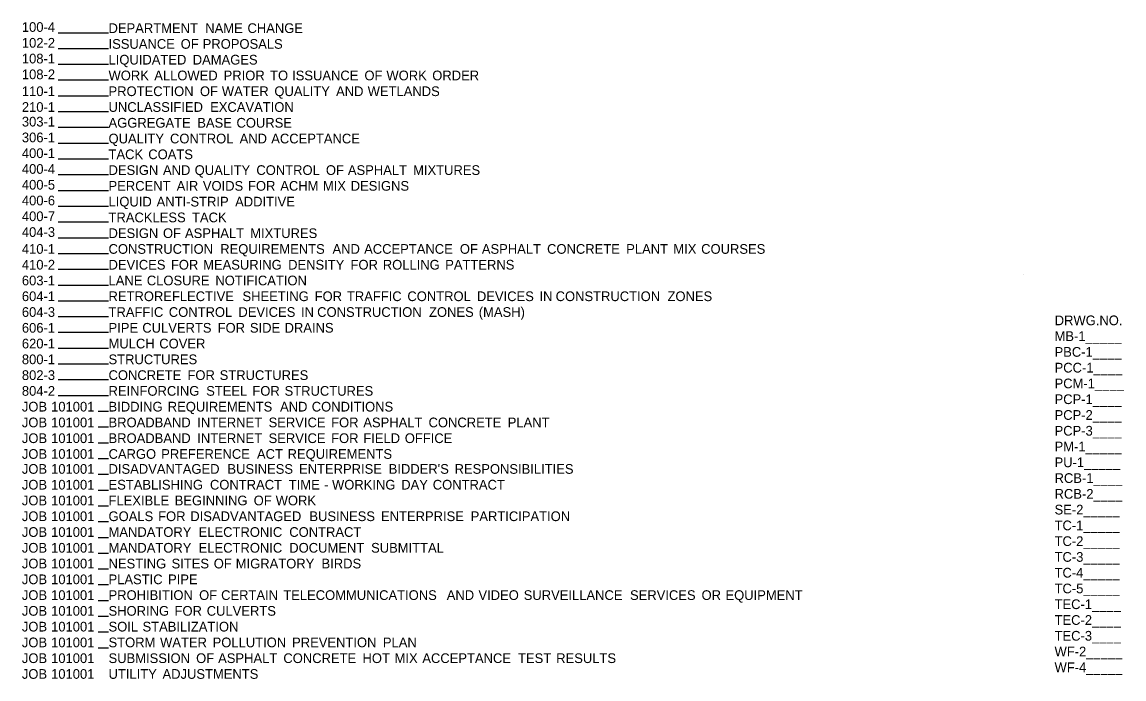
# Model space of a CAD drawing. Extents: x -1197 to 1681, y -1031 to 1021.
# Drawn here: x -1189 to 174, y -760 to 52 of the extents above; entities that cross this region are included whole.
import ezdxf

# ---------------------------------------------------------------- set-up
doc = ezdxf.new("R2010")
doc.units = 0
doc.layers.add('Default', color=7, linetype='Continuous')

msp = doc.modelspace()

# ---------------------------------------------------------------- linework, layer by layer
at = {"layer": 'Default'}
for p, q in [((-1081.7, 38.3), (-1144, 38.3)), ((-1081.7, 18.8), (-1144, 18.8)), ((-1081.7, -0.7), (-1144, -0.7)), ((-1081.7, -20.2), (-1144, -20.2)), ((-1081.7, -39.7), (-1144, -39.7)), ((-1081.7, -59.2), (-1144, -59.2)), ((-1081.7, -78.7), (-1144, -78.7)), ((-1081.7, -98.2), (-1144, -98.2)), ((-1081.7, -117.7), (-1144, -117.7)), ((-1081.7, -137.2), (-1144, -137.2)), ((-1081.7, -156.7), (-1144, -156.7)), ((-1081.7, -176.2), (-1144, -176.2)), ((-1081.7, -195.7), (-1144, -195.7)), ((-1081.7, -215.2), (-1144, -215.2)), ((-1081.7, -234.7), (-1144, -234.7)), ((-1081.7, -254.2), (-1144, -254.2)), ((50.5, -260), (50.5, -260)), ((-1081.7, -273.7), (-1144, -273.7)), ((-1081.7, -293.2), (-1144, -293.2)), ((-1081.7, -312.7), (-1144, -312.7)), ((-1081.7, -332.2), (-1144, -332.2)), ((-1081.7, -351.7), (-1144, -351.7)), ((-1081.7, -371.2), (-1144, -371.2)), ((-1081.7, -390.7), (-1144.2, -390.7)), ((-1081.7, -410.2), (-1144.2, -410.2)), ((-1081.7, -429.7), (-1094.4, -429.7)), ((-1081.7, -449.2), (-1094.4, -449.2)), ((-1081.7, -468.7), (-1094.4, -468.7)), ((-1081.7, -488.2), (-1094.4, -488.2)), ((-1081.7, -507.7), (-1094.4, -507.7)), ((-1081.7, -527.2), (-1094.4, -527.2)), ((-1081.7, -546.7), (-1094.4, -546.7)), ((-1081.7, -566.2), (-1094.4, -566.2)), ((-1081.7, -585.7), (-1094.4, -585.7)), ((-1081.7, -605.2), (-1094.4, -605.2)), ((-1081.7, -624.7), (-1094.4, -624.7)), ((-1081.7, -644.2), (-1094.4, -644.2)), ((-1081.7, -663.7), (-1094.4, -663.7)), ((-1081.7, -683.2), (-1094.4, -683.2)), ((-1081.7, -702.7), (-1094.4, -702.7)), ((-1081.7, -722.2), (-1094.4, -722.2))]:
    msp.add_line(p, q, dxfattribs=at)

# ---------------------------------------------------------------- texts
for s, p in [('100-4', (-1188.9, 39.7)), ('DEPARTMENT', (-1081.7, 38.3)), (' NAME', (-966.5, 38.3)), (' CHANGE', (-914.3, 38.3)), ('102-2', (-1188.9, 20.2)), ('ISSUANCE', (-1081.7, 18.8)), (' OF', (-996.9, 18.8)), (' PROPOSALS', (-969.7, 18.8)), ('108-1', (-1188.9, 0.7)), ('LIQUIDATED', (-1081.7, -0.7)), (' DAMAGES', (-982, -0.7)), ('108-2', (-1188.9, -18.8)), ('WORK', (-1081.7, -20.2)), (' ALLOWED', (-1029.6, -20.2)), (' PRIOR', (-943.8, -20.2)), (' TO', (-886.3, -20.2)), (' ISSUANCE', (-859.1, -20.2)), (' OF', (-769.6, -20.2)), (' WORK', (-742.4, -20.2)), (' ORDER', (-685.7, -20.2)), ('110-1', (-1188.9, -39.7)), ('PROTECTION', (-1081.7, -39.7)), (' OF', (-973.1, -39.7)), (' WATER', (-946, -39.7)), (' QUALITY', (-881, -39.7)), (' AND', (-804.7, -39.7)), (' WETLANDS', (-765.6, -39.7)), ('210-1', (-1188.9, -59.2)), ('UNCLASSIFIED', (-1081.7, -59.2)), (' EXCAVATION', (-960.5, -59.2)), ('303-1', (-1188.9, -77.3)), ('AGGREGATE', (-1081.7, -78.7)), (' BASE', (-976.4, -78.7)), (' COURSE', (-927.9, -78.7)), ('306-1', (-1188.9, -96.8)), ('QUALITY', (-1081.7, -98.2)), (' CONTROL', (-1010.1, -98.2)), (' AND', (-924, -98.2)), (' ACCEPTANCE', (-884.9, -98.2)), ('400-1', (-1188.9, -116.3)), ('TACK', (-1081.7, -117.7)), (' COATS', (-1037, -117.7)), ('400-4', (-1188.9, -135.8)), ('DESIGN', (-1081.7, -137.2)), (' AND', (-1018.8, -137.2)), (' QUALITY', (-979.6, -137.2)), (' CONTROL', (-903.3, -137.2)), (' OF', (-817.3, -137.2)), (' ASPHALT', (-790.1, -137.2)), (' MIXTURES', (-709.4, -137.2)), ('400-5', (-1188.9, -155.3)), ('PERCENT', (-1081.7, -156.7)), (' AIR', (-1001.9, -156.7)), (' VOIDS', (-969.5, -156.7)), (' FOR', (-913.6, -156.7)), (' ACHM', (-873.7, -156.7)), (' MIX', (-821, -156.7)), (' DESIGNS', (-786.6, -156.7)), ('400-6', (-1188.9, -174.8)), ('LIQUID', (-1081.7, -176.2)), (' ANTI-STRIP', (-1026.7, -176.2)), (' ADDITIVE', (-929.6, -176.2)), ('400-7', (-1188.9, -194.3)), ('TRACKLESS', (-1081.7, -195.7)), (' TACK', (-982.9, -195.7)), ('404-3', (-1188.9, -213.8)), ('DESIGN', (-1081.7, -215.2)), (' OF', (-1018.8, -215.2)), (' ASPHALT', (-991.6, -215.2)), (' MIXTURES', (-910.9, -215.2)), ('410-1', (-1188.9, -234.7)), ('CONSTRUCTION', (-1081.7, -234.7)), (' REQUIREMENTS', (-948, -234.7)), (' AND', (-809.1, -234.7)), (' ACCEPTANCE', (-770, -234.7)), (' OF', (-651.6, -234.7)), (' ASPHALT', (-624.4, -234.7)), (' CONCRETE', (-543.7, -234.7)), (' PLANT', (-445.8, -234.7)), (' MIX', (-387.5, -234.7)), (' COURSES', (-353.1, -234.7)), ('410-2', (-1188.9, -254.2)), ('DEVICES', (-1081.7, -254.2)), (' FOR', (-1009, -254.2)), (' MEASURING', (-969.1, -254.2)), (' DENSITY', (-864, -254.2)), (' FOR', (-786.8, -254.2)), (' ROLLING', (-746.9, -254.2)), (' PATTERNS', (-669.7, -254.2)), ('603-1', (-1188.9, -273.7)), ('LANE', (-1081.7, -273.7)), (' CLOSURE', (-1038.8, -273.7)), (' NOTIFICATION', (-954, -273.7)), ('604-1', (-1188.9, -293.2)), ('RETROREFLECTIVE', (-1081.7, -293.2)), (' SHEETING', (-920.5, -293.2)), (' FOR', (-831.2, -293.2)), (' TRAFFIC', (-791.3, -293.2)), (' CONTROL', (-716.5, -293.2)), (' DEVICES', (-630.5, -293.2)), (' IN', (-553.1, -293.2)), (' CONSTRUCTION', (-533.1, -293.2)), (' ZONES', (-394.7, -293.2)), ('604-3', (-1188.9, -312.7)), ('TRAFFIC', (-1081.7, -312.7)), (' CONTROL', (-1011.6, -312.7)), (' DEVICES', (-925.5, -312.7)), (' IN', (-848.1, -312.7)), (' CONSTRUCTION', (-828.1, -312.7)), (' ZONES', (-689.7, -312.7)), (' (MASH)', (-628.2, -312.7)), ('DRWG.NO.', (88.7, -323)), ('606-1', (-1188.9, -332.2)), ('PIPE', (-1081.7, -332.2)), (' CULVERTS', (-1044.4, -332.2)), (' FOR', (-951.2, -332.2)), (' SIDE', (-911.3, -332.2)), (' DRAINS', (-868.4, -332.2)), ('620-1', (-1188.9, -351.7)), ('MULCH', (-1081.7, -351.7)), (' COVER', (-1023.4, -351.7)), ('MB-1_____', (88.5, -342.5)), ('PBC-1____', (88.5, -362)), ('800-1', (-1188.9, -371.2)), ('STRUCTURES', (-1081.7, -371.2)), ('802-3', (-1188.9, -390.7)), ('CONCRETE', (-1081.7, -390.7)), (' FOR', (-988.5, -390.7)), (' STRUCTURES', (-948.7, -390.7)), ('PCC-1____', (88.5, -381.5)), ('PCM-1____', (88.5, -401)), ('804-2', (-1188.9, -410.2)), ('REINFORCING', (-1081.7, -410.2)), (' STEEL', (-965.4, -410.2)), (' FOR', (-908.2, -410.2)), (' STRUCTURES', (-868.4, -410.2)), ('PCP-1____', (88.5, -420.5)), ('JOB', (-1188.9, -429.7)), (' 101001', (-1157.2, -429.7)), ('BIDDING', (-1081.7, -429.7)), (' REQUIREMENTS', (-1012.9, -429.7)), (' AND', (-874, -429.7)), (' CONDITIONS', (-834.8, -429.7)), ('PCP-2____', (88.5, -440)), ('JOB', (-1188.9, -449.2)), (' 101001', (-1157.2, -449.2)), ('BROADBAND', (-1081.7, -449.2)), (' INTERNET', (-976.4, -449.2)), (' SERVICE', (-888.2, -449.2)), (' FOR', (-810.8, -449.2)), (' ASPHALT', (-771, -449.2)), (' CONCRETE', (-690.3, -449.2)), (' PLANT', (-592.4, -449.2)), ('PCP-3____', (88.5, -459.5)), ('JOB', (-1188.9, -468.7)), (' 101001', (-1157.2, -468.7)), ('BROADBAND', (-1081.7, -468.7)), (' INTERNET', (-976.4, -468.7)), (' SERVICE', (-888.2, -468.7)), (' FOR', (-810.8, -468.7)), (' FIELD', (-771, -468.7)), (' OFFICE', (-719.7, -468.7)), ('JOB', (-1188.9, -488.2)), (' 101001', (-1157.2, -488.2)), ('CARGO', (-1081.7, -488.2)), (' PREFERENCE', (-1021, -488.2)), (' ACT', (-902.6, -488.2)), (' REQUIREMENTS', (-864.7, -488.2)), ('PM-1_____', (88.5, -479)), ('PU-1_____', (88.5, -498.5)), ('JOB', (-1188.9, -506.7)), (' 101001', (-1157.2, -506.7)), ('DISADVANTAGED', (-1081.7, -506.7)), (' BUSINESS', (-939.1, -506.7)), (' ENTERPRISE', (-850.5, -506.7)), (" BIDDER'S", (-739.6, -506.7)), (' RESPONSIBILITIES', (-658.1, -506.7)), ('JOB', (-1188.9, -526.2)), (' 101001', (-1157.2, -526.2)), ('ESTABLISHING', (-1081.7, -526.2)), (' CONTRACT', (-960.7, -526.2)), (' TIME', (-863.2, -526.2)), (' WORKING', (-809.7, -526.2)), (' DAY', (-724.1, -526.2)), (' CONTRACT', (-685.1, -526.2)), ('RCB-1____', (88.5, -518)), (' -', (-819.4, -526.2)), ('RCB-2____', (88.5, -537.5)), ('JOB', (-1188.9, -545.7)), (' 101001', (-1157.2, -545.7)), ('FLEXIBLE', (-1081.7, -545.7)), (' BEGINNING', (-1004.3, -545.7)), (' OF', (-906.6, -545.7)), (' WORK', (-879.4, -545.7)), ('SE-2_____', (88.5, -557)), ('JOB', (-1188.9, -565.2)), (' 101001', (-1157.2, -565.2)), ('GOALS', (-1081.7, -565.2)), (' FOR', (-1024.8, -565.2)), (' DISADVANTAGED', (-985, -565.2)), (' BUSINESS', (-837.7, -565.2)), (' ENTERPRISE', (-749.1, -565.2)), (' PARTICIPATION', (-638.2, -565.2)), ('TC-1_____', (88.5, -576.5)), ('JOB', (-1188.9, -584.7)), (' 101001', (-1157.2, -584.7)), ('MANDATORY', (-1081.7, -584.7)), (' ELECTRONIC', (-974.7, -584.7)), (' CONTRACT', (-862.6, -584.7)), ('TC-2_____', (88.5, -596)), ('JOB', (-1188.9, -604.2)), (' 101001', (-1157.2, -604.2)), ('MANDATORY', (-1081.7, -604.2)), (' ELECTRONIC', (-974.7, -604.2)), (' DOCUMENT', (-862.6, -604.2)), (' SUBMITTAL', (-761.4, -604.2)), ('JOB', (-1188.9, -623.7)), (' 101001', (-1157.2, -623.7)), ('NESTING', (-1081.7, -623.7)), (' SITES', (-1008.2, -623.7)), (' OF', (-956, -623.7)), (' MIGRATORY', (-928.8, -623.7)), (' BIRDS', (-822.7, -623.7)), ('TC-3_____', (88.5, -615.5)), ('TC-4_____', (88.5, -635)), ('JOB', (-1188.9, -643.2)), (' 101001', (-1157.2, -643.2)), ('PLASTIC', (-1081.7, -643.2)), (' PIPE', (-1012.5, -643.2)), ('JOB', (-1188.9, -662.7)), (' 101001', (-1157.2, -662.7)), ('PROHIBITION', (-1081.7, -662.7)), (' OF', (-974.1, -662.7)), (' CERTAIN', (-946.9, -662.7)), (' TELECOMMUNICATIONS', (-870, -662.7)), (' AND', (-667.8, -662.7)), (' VIDEO', (-628.6, -662.7)), (' SURVEILLANCE', (-572.6, -662.7)), (' SERVICES', (-441.1, -662.7)), (' OR', (-352.6, -662.7)), (' EQUIPMENT', (-323, -662.7)), ('TC-5_____', (88.5, -654.5)), ('TEC-1____', (88.5, -674)), ('JOB', (-1188.9, -682.2)), (' 101001', (-1157.2, -682.2)), ('SHORING', (-1081.7, -682.2)), (' FOR', (-1004.5, -682.2)), (' CULVERTS', (-964.7, -682.2)), ('TEC-2____', (88.5, -693.5)), ('JOB', (-1188.9, -701.7)), (' 101001', (-1157.2, -701.7)), ('SOIL', (-1081.7, -701.7)), (' STABILIZATION', (-1044.1, -701.7)), ('TEC-3____', (88.5, -713)), ('JOB', (-1188.9, -721.2)), (' 101001', (-1157.2, -721.2)), ('STORM', (-1081.7, -721.2)), (' WATER', (-1022.4, -721.2)), (' POLLUTION', (-957.4, -721.2)), (' PREVENTION', (-859.1, -721.2)), (' PLAN', (-746.8, -721.2)), ('WF-2_____', (88.5, -732.5)), ('JOB', (-1188.9, -740.7)), (' 101001', (-1157.2, -740.7)), ('SUBMISSION', (-1081.7, -740.7)), (' OF', (-977.8, -740.7)), (' ASPHALT', (-950.6, -740.7)), (' CONCRETE', (-869.9, -740.7)), (' HOT', (-772, -740.7)), (' MIX', (-732.3, -740.7)), (' ACCEPTANCE', (-698, -740.7)), (' TEST', (-579.6, -740.7)), (' RESULTS', (-532.4, -740.7)), ('JOB', (-1188.9, -760.2)), (' 101001', (-1157.2, -760.2)), ('UTILITY', (-1081.7, -760.2)), (' ADJUSTMENTS', (-1019.4, -760.2)), ('WF-4_____', (88.5, -752))]:
    msp.add_text(s, height=12, dxfattribs=at).set_placement(p)

doc.saveas('drawing.dxf')
